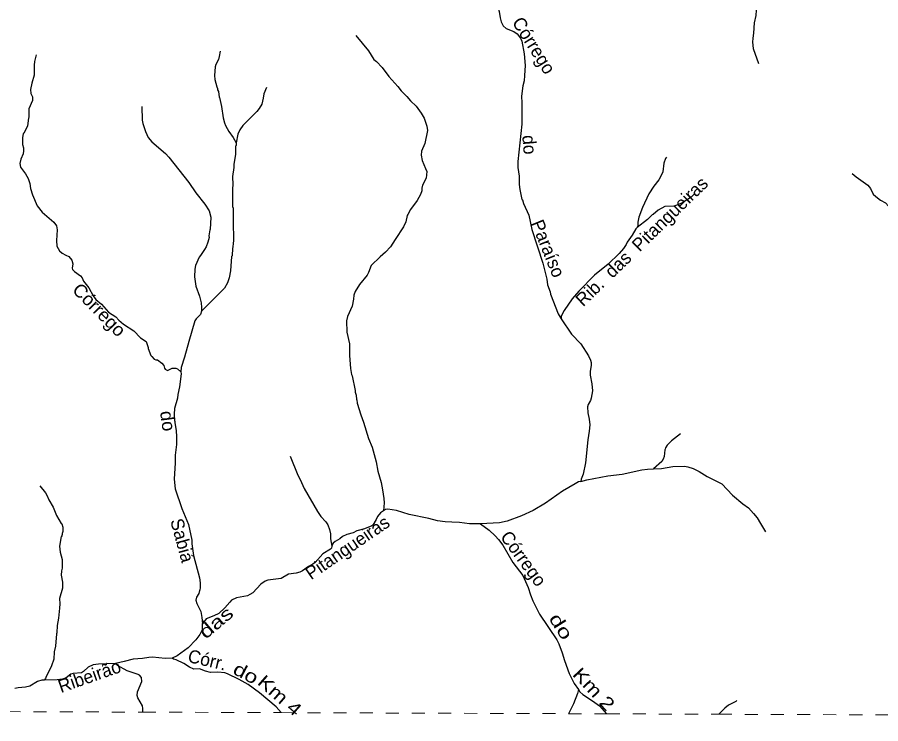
# Model space of a CAD drawing. Extents: x 551.6 to 577.6, y 7567 to 7594.7.
# Drawn here: x 555.19 to 561.8, y 7566.95 to 7572.36 of the extents above; entities that cross this region are included whole.
import ezdxf
from ezdxf.enums import TextEntityAlignment as Align

# ---------------------------------------------------------------- set-up
doc = ezdxf.new("R2010")
doc.units = 0
doc.header["$LTSCALE"] = 0.04
doc.linetypes.add('SHORT_DASHED', pattern=[2.7, 1.5, -1.2])
doc.layers.add('53', color=7, linetype='SHORT_DASHED', lineweight=13)
doc.layers.add('7', color=7, linetype='Continuous', lineweight=25)
doc.layers.add('61', color=7, linetype='Continuous')

msp = doc.modelspace()

# ---------------------------------------------------------------- linework, layer by layer
at = {"layer": '53'}
msp.add_lwpolyline([(551.613, 7567.0572), (552.9162, 7567.0524), (553.7221, 7567.0495), (554.9107, 7567.0451), (556.1477, 7567.0406), (557.2075, 7567.0367), (559.4055, 7567.0287), (559.6981, 7567.0276), (560.556, 7567.0244), (562.9715, 7567.0156), (564.6334, 7567.0092), (566.4358, 7567.0011), (566.7714, 7566.9996), (570.8595, 7566.9812), (572.5416, 7566.9737), (572.8363, 7566.9724), (573.5039, 7566.9694), (573.609, 7566.9689), (574.6855, 7566.9641), (575.0536, 7566.9624), (576.5544, 7566.9557), (577.1266, 7566.9531), (577.4204, 7566.9518)], dxfattribs=at)
at = {"layer": '7'}
for points in [[(558.6981, 7572.8757), (558.7359, 7572.8419), (558.756, 7572.8177), (558.7713, 7572.7952), (558.8164, 7572.7067), (558.8236, 7572.668), (558.8196, 7572.5763), (558.8228, 7572.5312), (558.8614, 7572.4524), (558.8759, 7572.4025), (558.8824, 7572.3542), (558.892, 7572.3236), (558.9057, 7572.2946), (558.9291, 7572.2721), (558.987, 7572.2511), (559.0135, 7572.2326), (559.0393, 7572.198), (559.0482, 7572.1755), (559.0675, 7572.0789), (559.0739, 7571.9904), (559.0691, 7571.9131)], [(560.8477, 7572.4974), (560.8396, 7572.3735), (560.8284, 7572.3171), (560.8236, 7572.2367), (560.8163, 7572.198), (560.8147, 7572.1691), (560.8211, 7572.1208), (560.8622, 7572.0057)], [(557.779, 7572.2198), (557.8748, 7572.1031), (557.9166, 7572.0371), (557.9375, 7572.021), (557.9794, 7571.9751), (558.0301, 7571.9067), (558.0993, 7571.8294), (558.1243, 7571.7972), (558.1677, 7571.7538), (558.1959, 7571.72), (558.2393, 7571.6781), (558.2788, 7571.625), (558.3013, 7571.5864), (558.3206, 7571.5252), (558.3255, 7571.4914), (558.3053, 7571.3924), (558.282, 7571.3337), (558.2788, 7571.3047), (558.2868, 7571.2629), (558.3126, 7571.2025)], [(555.3316, 7572.0717), (555.3179, 7572.0194), (555.3147, 7571.992), (555.3147, 7571.9147), (555.2978, 7571.8552), (555.2881, 7571.8053), (555.2897, 7571.7763), (555.3018, 7571.7506), (555.3026, 7571.7232), (555.2737, 7571.6588), (555.2753, 7571.5928), (555.272, 7571.5872), (555.264, 7571.5284), (555.235, 7571.4705), (555.2318, 7571.4689), (555.227, 7571.4367), (555.227, 7571.3852), (555.2334, 7571.3594), (555.2334, 7571.3369)], [(556.7392, 7572.099), (556.7328, 7572.058), (556.7255, 7572.0355), (556.7062, 7571.9984), (556.7014, 7571.9791), (556.6965, 7571.9131), (556.6981, 7571.8826), (556.7126, 7571.827), (556.7191, 7571.8133), (556.7191, 7571.8045), (556.7255, 7571.7908), (556.7319, 7571.7482), (556.7352, 7571.7441), (556.7497, 7571.6765), (556.7625, 7571.5896), (556.7722, 7571.551), (556.7802, 7571.5301), (556.8052, 7571.485), (556.8398, 7571.4399), (556.8612, 7571.3987)], [(559.0691, 7571.9131), (559.0667, 7571.8729), (559.0578, 7571.8343), (559.0466, 7571.7546), (559.049, 7571.7039), (559.0482, 7571.5397), (559.0176, 7571.2548), (559.0184, 7571.2097), (559.0288, 7571.1421), (559.0288, 7571.0794), (559.0337, 7571.0407), (559.0498, 7570.9635), (559.053, 7570.9619), (559.0626, 7570.9345)], [(557.0949, 7571.8222), (557.0732, 7571.7731), (557.0692, 7571.7393), (557.0571, 7571.6942), (557.0378, 7571.6604), (557.0193, 7571.6379), (556.913, 7571.5309), (556.8897, 7571.4979), (556.8744, 7571.4641), (556.8612, 7571.3987)], [(556.1396, 7571.6757), (556.1428, 7571.5719), (556.1461, 7571.5462), (556.167, 7571.485), (556.1887, 7571.4399), (556.2161, 7571.4053), (556.3207, 7571.3152), (556.3464, 7571.2886), (556.4986, 7571.0955), (556.5525, 7571.0142), (556.6225, 7570.9273), (556.6547, 7570.8782), (556.6676, 7570.8283), (556.6627, 7570.7341), (556.6595, 7570.7309), (556.6531, 7570.6866), (556.6547, 7570.6737), (556.6458, 7570.6367), (556.6313, 7570.6029), (556.6201, 7570.5804), (556.5879, 7570.5353)], [(556.8612, 7571.3987), (556.8607, 7571.3787), (556.8575, 7571.3731), (556.8559, 7571.3111), (556.8438, 7571.2323), (556.8446, 7571.2097), (556.835, 7571.1405), (556.8366, 7571.0778), (556.8334, 7571.0488), (556.8326, 7570.9554), (556.835, 7570.9104), (556.8382, 7570.8991), (556.8398, 7570.8025)], [(555.2334, 7571.3369), (555.231, 7571.3128), (555.2133, 7571.2725), (555.2044, 7571.2403), (555.2117, 7571.2114), (555.2487, 7571.1598), (555.2688, 7571.126), (555.2817, 7571.0874), (555.2881, 7571.0488), (555.3026, 7571.0005), (555.3388, 7570.9152), (555.3759, 7570.8677), (555.466, 7570.792), (555.4861, 7570.7623), (555.4926, 7570.7333), (555.4853, 7570.6496), (555.4877, 7570.6078), (555.5095, 7570.5707), (555.5288, 7570.5546), (555.5586, 7570.5385)], [(560.1564, 7571.2878), (560.1491, 7571.2773), (560.1363, 7571.2435), (560.1274, 7571.1759), (560.1153, 7571.147), (560.0984, 7571.1156), (560.059, 7571.0657), (560.022, 7571.0077), (559.9721, 7570.9023), (559.9447, 7570.8283), (559.9383, 7570.7896), (559.9375, 7570.7639), (559.9324, 7570.7504)], [(558.3126, 7571.2025), (558.3222, 7571.1792), (558.3174, 7571.1285), (558.2916, 7571.0802), (558.2916, 7571.0753), (558.2884, 7571.0737), (558.2828, 7571.0504), (558.2836, 7571.0311), (558.2739, 7571.0021), (558.2482, 7570.9578), (558.1959, 7570.8878), (558.1774, 7570.85), (558.1701, 7570.8411), (558.1597, 7570.7929), (558.1428, 7570.7542), (558.0784, 7570.6593), (558.043, 7570.6013), (558.0052, 7570.5603), (557.9641, 7570.5257), (557.8965, 7570.4597), (557.8748, 7570.4066)], [(561.5793, 7571.1639), (561.6099, 7571.1373), (561.6968, 7571.0729), (561.7177, 7571.0488), (561.7394, 7571.0061), (561.7587, 7570.986), (561.795, 7570.9594), (561.832, 7570.9393), (561.8802, 7570.8878), (561.9479, 7570.8411), (562.0018, 7570.7952), (562.129, 7570.7107), (562.1547, 7570.6979), (562.2239, 7570.6721), (562.2577, 7570.6552), (562.3307, 7570.6292)], [(560.3705, 7571.0077), (560.3455, 7570.9828), (560.2731, 7570.9369), (560.2151, 7570.9144), (560.1443, 7570.9103), (560.0928, 7570.8838), (560.0542, 7570.85), (560.0461, 7570.8468), (560.0107, 7570.8114), (559.9324, 7570.7504)], [(559.0626, 7570.9345), (559.1029, 7570.8444), (559.1254, 7570.7349), (559.2091, 7570.4774), (559.2397, 7570.355), (559.2461, 7570.31), (559.2647, 7570.2585), (559.2687, 7570.2392), (559.3282, 7570.0879), (559.3499, 7570.0516)], [(556.8398, 7570.8025), (556.8414, 7570.6448), (556.8382, 7570.6335), (556.8366, 7570.5965), (556.8334, 7570.5917), (556.8301, 7570.5337), (556.8269, 7570.5289), (556.8173, 7570.4178), (556.8076, 7570.3647), (556.7947, 7570.3261), (556.7722, 7570.2866), (556.5962, 7570.1103)], [(559.9324, 7570.7504), (559.9214, 7570.7405), (559.8932, 7570.6915), (559.8546, 7570.6383), (559.8473, 7570.619), (559.8264, 7570.5884), (559.7942, 7570.5498), (559.7097, 7570.4685)], [(555.5586, 7570.5385), (555.5795, 7570.5273), (555.6036, 7570.4999), (555.6109, 7570.4725), (555.606, 7570.4387), (555.6093, 7570.4283), (555.6229, 7570.413), (555.6712, 7570.3808), (555.6817, 7570.3647), (555.6921, 7570.3381), (555.7332, 7570.2874), (555.767, 7570.2271), (555.7871, 7570.1989), (555.8314, 7570.1635), (555.8845, 7570.1023), (555.94, 7570.0653), (555.9626, 7570.0403), (555.9988, 7570.009), (556.0785, 7569.9591), (556.1284, 7569.9059)], [(556.5879, 7570.5353), (556.579, 7570.5224), (556.5517, 7570.4581), (556.5452, 7570.4323), (556.5436, 7570.3728), (556.5541, 7570.3019), (556.5806, 7570.2247), (556.5935, 7570.1732), (556.5975, 7570.1378), (556.5962, 7570.1103)], [(559.7097, 7570.4685), (559.6051, 7570.3848), (559.4852, 7570.2617), (559.4353, 7570.2045), (559.3725, 7570.1136), (559.3508, 7570.0701), (559.3499, 7570.0516)], [(557.8748, 7570.4066), (557.8643, 7570.384), (557.8064, 7570.3148), (557.7734, 7570.2601), (557.7621, 7570.2311), (557.7605, 7570.2021), (557.7508, 7570.1474), (557.7138, 7570.0685), (557.7074, 7570.0363), (557.709, 7569.9478), (557.7283, 7569.8593), (557.7283, 7569.7692), (557.7379, 7569.671), (557.7444, 7569.6259), (557.7492, 7569.6146), (557.7717, 7569.502), (557.7717, 7569.4907), (557.7798, 7569.4657), (557.783, 7569.4327), (557.7854, 7569.4311)], [(556.5962, 7570.1103), (556.5887, 7570.0846), (556.5557, 7570.0516), (556.5452, 7570.0347), (556.4986, 7569.877)], [(559.3499, 7570.0516), (559.4304, 7569.9333), (559.5005, 7569.8601), (559.56, 7569.7683), (559.5745, 7569.7354), (559.5793, 7569.716), (559.5801, 7569.6967), (559.5729, 7569.6484)], [(556.1284, 7569.9059), (556.1718, 7569.8762), (556.1879, 7569.8319), (556.1879, 7569.8239), (556.2088, 7569.7708), (556.2153, 7569.7619), (556.2346, 7569.7434), (556.2459, 7569.7378), (556.2595, 7569.7361), (556.2917, 7569.712), (556.307, 7569.6943), (556.3126, 7569.6726), (556.3183, 7569.6653), (556.3368, 7569.6565), (556.373, 7569.6726), (556.3988, 7569.6734), (556.4117, 7569.6685), (556.4374, 7569.6452)], [(556.4986, 7569.877), (556.4664, 7569.7563), (556.4406, 7569.679), (556.4374, 7569.6452)], [(556.4374, 7569.6452), (556.4414, 7569.6307), (556.4277, 7569.5293), (556.4149, 7569.4714), (556.4116, 7569.4424), (556.3907, 7569.3651), (556.3875, 7569.3201), (556.3891, 7569.2702), (556.3923, 7569.267), (556.3923, 7569.2541), (556.4036, 7569.1961), (556.4052, 7569.1478), (556.4052, 7569.0899), (556.3955, 7569.0078), (556.3939, 7568.9499)], [(559.5729, 7569.6484), (559.5729, 7569.6195), (559.5858, 7569.5535), (559.589, 7569.5003), (559.5801, 7569.444), (559.5737, 7569.4247), (559.5568, 7569.3949), (559.552, 7569.3764), (559.5536, 7569.3313), (559.5648, 7569.2831), (559.5689, 7569.2396), (559.5648, 7569.1913), (559.5536, 7569.1237), (559.5367, 7568.9483), (559.5182, 7568.8629), (559.5037, 7568.8243), (559.4997, 7568.8053)], [(557.7854, 7569.4311), (557.7895, 7569.4054), (557.8152, 7569.3169), (557.8361, 7569.2605), (557.8748, 7569.135), (557.9021, 7569.069), (557.9343, 7568.9563), (557.9456, 7568.8839), (557.9713, 7568.7986), (557.9826, 7568.7422), (557.9923, 7568.6746), (557.9939, 7568.6424), (557.9894, 7568.5809)], [(560.2626, 7569.1704), (560.1942, 7569.1172), (560.162, 7569.0835), (560.1491, 7569.0641), (560.1475, 7569.0537), (560.1427, 7569.0472), (560.1379, 7568.9982), (560.1314, 7568.9772), (560.121, 7568.9579), (560.0581, 7568.9025)], [(557.2744, 7568.999), (557.3331, 7568.8549), (557.3516, 7568.8211), (557.3814, 7568.7535), (557.4836, 7568.5756), (557.5102, 7568.5378), (557.5472, 7568.4976), (557.5625, 7568.4734), (557.5754, 7568.4396), (557.5834, 7568.4058), (557.5834, 7568.3672), (557.5947, 7568.3102)], [(556.3939, 7568.9499), (556.3867, 7568.8243), (556.3955, 7568.7487), (556.4446, 7568.599), (556.4977, 7568.4766), (556.5227, 7568.3575), (556.5235, 7568.3286), (556.5356, 7568.24), (556.5823, 7568.0678), (556.5871, 7568.0292), (556.5863, 7567.9953)], [(559.4997, 7568.8053), (559.5472, 7568.8187), (559.7081, 7568.8493), (559.816, 7568.8613), (559.9673, 7568.8951), (560.0123, 7568.9008), (560.0581, 7568.9025)], [(560.0581, 7568.9025), (560.1186, 7568.9048), (560.2055, 7568.9201), (560.2956, 7568.9225), (560.3198, 7568.9193), (560.36, 7568.9064), (560.4067, 7568.8831)], [(560.4067, 7568.8831), (560.4678, 7568.8444), (560.5797, 7568.7881), (560.6626, 7568.702), (560.7415, 7568.6352), (560.7833, 7568.6046), (560.8236, 7568.5611), (560.8501, 7568.5265), (560.8775, 7568.4847), (560.9137, 7568.4195)], [(555.3598, 7568.772), (555.4024, 7568.7197), (555.4153, 7568.6972), (555.4282, 7568.6666), (555.4604, 7568.6086), (555.4869, 7568.5459), (555.5223, 7568.4855), (555.528, 7568.4815), (555.536, 7568.4557), (555.536, 7568.4235), (555.5296, 7568.4082), (555.5296, 7568.3986), (555.5264, 7568.3962), (555.5264, 7568.3857), (555.5231, 7568.3841), (555.5103, 7568.3109), (555.5151, 7568.2658), (555.5296, 7568.2095), (555.5296, 7568.1435), (555.5239, 7568.1209), (555.5215, 7568.0887), (555.5312, 7568.0356), (555.5312, 7567.9905), (555.5103, 7567.9101), (555.5119, 7567.8682), (555.5087, 7567.836)], [(559.4565, 7568.7875), (559.3604, 7568.7309), (559.2301, 7568.6408), (559.1351, 7568.5845), (559.0466, 7568.5426), (558.9371, 7568.5024), (558.8792, 7568.4895), (558.7321, 7568.482)], [(559.4997, 7568.8053), (559.4819, 7568.8031), (559.4565, 7568.7875)], [(557.9894, 7568.5809), (557.9673, 7568.5668), (557.944, 7568.537), (557.9343, 7568.5137), (557.9086, 7568.4718), (557.9005, 7568.4662), (557.8442, 7568.4444), (557.7863, 7568.4283), (557.7573, 7568.4139), (557.709, 7568.401), (557.6768, 7568.3857), (557.6551, 7568.3672)], [(558.5138, 7568.4943), (558.4623, 7568.4975), (558.4043, 7568.5056), (558.3367, 7568.5233), (558.187, 7568.5531), (558.0905, 7568.5845), (558.0229, 7568.5941), (558.0052, 7568.5909), (557.9894, 7568.5809)], [(558.7321, 7568.482), (558.649, 7568.4815), (558.5717, 7568.4919), (558.5138, 7568.4943)], [(558.7321, 7568.482), (558.7995, 7568.434), (558.8454, 7568.3905), (558.8711, 7568.3608), (558.9033, 7568.3189), (558.9806, 7568.1869), (559.0562, 7568.0855), (559.0981, 7567.9938), (559.1142, 7567.9374), (559.1327, 7567.8924), (559.1834, 7567.7893), (559.3178, 7567.593), (559.3331, 7567.564), (559.3588, 7567.4932)], [(557.6551, 7568.3672), (557.6197, 7568.3462), (557.6044, 7568.3334), (557.5995, 7568.3269), (557.5947, 7568.3102)], [(557.5947, 7568.3102), (557.5907, 7568.2964), (557.5842, 7568.2875), (557.5263, 7568.2529), (557.4676, 7568.1861), (557.4498, 7568.1724), (557.416, 7568.1555), (557.3694, 7568.1209), (557.3501, 7568.1112), (557.3211, 7568.1032), (557.2631, 7568.096), (557.2052, 7568.0646), (557.1038, 7568.0501), (557.0845, 7568.0436), (557.0498, 7568.0203), (556.9887, 7567.9543), (556.967, 7567.9398), (556.9477, 7567.931), (556.8656, 7567.9149), (556.8269, 7567.8964), (556.8124, 7567.8827)], [(556.5863, 7567.9953), (556.5839, 7567.9744), (556.5806, 7567.972), (556.5758, 7567.9487), (556.5589, 7567.9197), (556.5533, 7567.8964), (556.5597, 7567.8714), (556.5911, 7567.8119), (556.6, 7567.7636), (556.6034, 7567.7174)], [(556.8124, 7567.8827), (556.7754, 7567.8384), (556.7279, 7567.7966), (556.6917, 7567.7781), (556.6322, 7567.7539), (556.6034, 7567.7174)], [(555.5087, 7567.836), (555.5006, 7567.7588), (555.4909, 7567.7024), (555.4893, 7567.6469), (555.4861, 7567.6397), (555.4781, 7567.5463), (555.4684, 7567.5012), (555.4652, 7567.4449), (555.4475, 7567.395), (555.4258, 7567.3467), (555.408, 7567.3145), (555.4024, 7567.2976), (555.3912, 7567.2851)], [(556.6034, 7567.7174), (556.612, 7567.7394), (556.6016, 7567.7129), (556.6016, 7567.671), (556.5831, 7567.6348), (556.5541, 7567.5938), (556.4937, 7567.5334), (556.4092, 7567.4706), (556.3712, 7567.4541)], [(556.3712, 7567.4541), (556.3183, 7567.4513), (556.2217, 7567.4602), (556.1928, 7567.4594), (556.1445, 7567.4513), (556.072, 7567.4449), (556.0044, 7567.4288), (555.939, 7567.4139)], [(557.2075, 7567.0367), (557.169, 7567.0819), (557.041, 7567.1881), (556.9525, 7567.2533), (556.8849, 7567.2912), (556.7947, 7567.3338), (556.7738, 7567.3402), (556.7223, 7567.3459), (556.666, 7567.3443), (556.6265, 7567.3531), (556.5807, 7567.3732), (556.5372, 7567.3692), (556.5042, 7567.3845), (556.4599, 7567.4127), (556.4036, 7567.44), (556.3809, 7567.4452), (556.3712, 7567.4541)], [(559.3588, 7567.4932), (559.3749, 7567.4368), (559.4103, 7567.337), (559.4506, 7567.2598), (559.4826, 7567.2135)], [(555.939, 7567.4139), (555.8081, 7567.4079), (555.7678, 7567.403), (555.7284, 7567.3853), (555.6921, 7567.3507), (555.6777, 7567.3419), (555.6149, 7567.3354), (555.5956, 7567.3306), (555.5594, 7567.304), (555.5328, 7567.2928), (555.4926, 7567.2879), (555.3912, 7567.2851)], [(556.1477, 7567.0406), (556.1477, 7567.0682), (556.1436, 7567.0876), (556.1082, 7567.1503), (556.1026, 7567.168), (556.1058, 7567.197), (556.1396, 7567.2759), (556.138, 7567.3049), (556.1219, 7567.3233), (556.1123, 7567.3298), (556.027, 7567.3563), (555.9545, 7567.3982), (555.939, 7567.4139)], [(555.3912, 7567.2851), (555.3751, 7567.2847), (555.3413, 7567.2743), (555.2825, 7567.2388), (555.2479, 7567.2316), (555.1916, 7567.2276), (555.1674, 7567.2211)], [(559.4826, 7567.2135), (559.4747, 7567.1825), (559.4433, 7567.1037), (559.4055, 7567.0287)], [(559.4826, 7567.2135), (559.494, 7567.197), (559.5157, 7567.1753), (559.5906, 7567.1278), (559.6437, 7567.0883), (559.6981, 7567.0276)], [(560.6948, 7567.1302), (560.6868, 7567.1222), (560.6304, 7567.0932), (560.6022, 7567.0714), (560.556, 7567.0244)]]:
    msp.add_lwpolyline(points, dxfattribs=at)

# ---------------------------------------------------------------- texts
at = {"layer": '61'}
for s, rotation, p in [('Córrego', 302.195, (559.099, 7572.1168)), ('do', 274.584, (559.0579, 7571.3798)), ('Rib.  das  Pitangueiras', 44.158, (560.0012, 7570.6076)), ('Paraíso', 292.008, (559.2038, 7570.5707)), ('Sabiá', 285.21, (556.4011, 7568.3421)), ('Pitangueiras', 34.4, (557.7417, 7568.2595)), ('Córrego', 306.169, (559.0214, 7568.1865)), ('Córr.', 346.824, (556.6295, 7567.3921)), ('Ribeirão', 19.241, (555.7549, 7567.2682))]:
    msp.add_text(s, height=0.1, rotation=rotation, dxfattribs=at).set_placement(p, align=Align.CENTER)
for s, rotation, width, p in [('Córrego', 314.646, 1.05, (555.7778, 7570.0849)), ('do', 277.837, 1.05, (556.2894, 7569.2625)), ('das', 40.163, 1.35, (556.7398, 7567.6885)), ('do', 302.272, 1.4, (559.3072, 7567.6699)), ('do', 332.074, 1.3, (556.913, 7567.2946)), ('Km 2', 313.236, 1.25, (559.5639, 7567.1826)), ('Km 4', 318.661, 1.25, (557.163, 7567.1305))]:
    msp.add_text(s, height=0.1, rotation=rotation, dxfattribs=dict(at, width=width)).set_placement(p, align=Align.CENTER)

doc.saveas('drawing.dxf')
